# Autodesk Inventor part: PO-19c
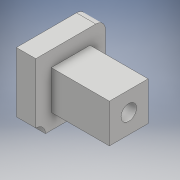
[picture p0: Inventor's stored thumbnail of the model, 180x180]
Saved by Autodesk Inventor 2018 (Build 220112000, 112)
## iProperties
Created: 2020-01
Part Number: PO-19c
Material: Générique
Document SubType Name: Modeling
Designer: TJ
Density: 1 g/cm^3
Appearance: Par défaut
Author: TJ
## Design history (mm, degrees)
sketch "Esquisse1"
  geometry: L1 (18, 18)-(-18, 18); L2 (-18, 18)-(-18, -18); L3 (-18, -18)-(18, -18); L4 (18, -18)-(18, 18); 1 further point
  constraints: 8 end point, 2 parallel, 1 horizontal, 1 perpendicular
  dimensions: "d0" = 36 distance of L3.end L1.start; "d1" = 36 distance of L1.start L1.end (= d0); "d2" = 18 distance from line of L4 point (0, 0) (= 0.5 x d0); "d3" = 18 distance from line of L1 point (0, 0) (= 0.5 x d0)
extrude "Extrusion1" new body sketch "Esquisse1" distance "d4" = 10; taper "d5" = 0 deg
sketch "Esquisse3"
  geometry: L1 (-10, 10)-(10, 10); L2 (10, 10)-(10, -10); L3 (10, -10)-(-10, -10); L4 (-10, -10)-(-10, 10); L5 (-10, 10)-(10, -10); L6 (10, 10)-(-10, -10); 1 further point
  constraints: 12 end point, 2 midpoint, 2 parallel, 1 horizontal, 1 perpendicular
  dimensions: "d10" = 20 distance of L1.start L1.end; "d11" = 20 distance of L3.end L1.start (= d10)
extrude "Extrusion3" join sketch "Esquisse3" distance "d12" = 30; taper "d13" = 0 deg
sketch "Esquisse5"
  geometry: L1 (-4, -4)-(4, -4); L2 (4, -4)-(4, 4); L3 (4, 4)-(-4, 4); L4 (-4, 4)-(-4, -4); L5 (-4, -4)-(4, 4); L6 (4, -4)-(-4, 4); 1 further point
  constraints: 12 end point, 2 midpoint, 2 parallel, 1 horizontal, 1 perpendicular
  dimensions: "d17" = 8 distance of L3.end L1.start; "d18" = 8 distance of L2.end L3.end
extrude "Extrusion5" cut sketch "Esquisse5" extent not by distance; stored distance "d19" = 10; taper "d20" = 0 deg
fillet "Congé2" dims "d21" = 5
fillet "Congé3" dims "d25" = 4
sketch "Esquisse6"
  geometry: L1 (-18, -18)-(18, -18) reference; C1 r 5 at (18, -18); 1 further point
  constraints: 1 centre point
  dimensions: "d26" = 10 diameter of C1
extrude "Extrusion6" cut sketch "Esquisse6" extent not by distance; stored distance "d27" = 10; taper "d28" = 0 deg
node "Solide1"
